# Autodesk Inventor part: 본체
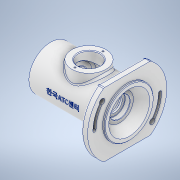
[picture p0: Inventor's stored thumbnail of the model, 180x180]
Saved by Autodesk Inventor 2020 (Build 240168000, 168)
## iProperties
Created: 2022-05
Part Number: 본체
Material: 알루미늄 6061
Document SubType Name: Modeling
Designer: Student
Mass: 685.464 g
Surface Area: 627.299 cm^2
Volume: 253.876 cm^3
Density: 2.7 g/cm^3
Appearance: 알루미늄 - 평지
Author: Student
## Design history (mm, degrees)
sketch "스케치1"
  geometry: L1 (-97.293, 0)-(97.293, 0); L2 (-51, 0)-(-51, 32); L3 (-51, 32)-(51, 32); L4 (51, 32)-(51, 58); L5 (51, 58)-(61, 58); L6 (61, 58)-(61, 36); L7 (61, 36)-(64, 36); L8 (64, 36)-(64, 0); 4 further points
  constraints: 16 end point, 4 perpendicular, 3 coincident, 3 midpoint, 2 horizontal, 2 point on line, 1 parallel, 1 vertical, 1 vertical alignment
  dimensions: "d5" = 64 diameter of L3 L1; "d6" = 116 diameter of L5 L1; "d7" = 72 diameter of L7 L1; "d8" = 102 distance between parallel lines of L4 L2; "d9" = 13 distance between parallel lines of L8 L4; "d10" = 3 distance of L6.end L7.end
revolve "회전1" sketch "스케치1" stored, may be unused: angle "d11" = 90 deg
sketch "스케치2"
  geometry: L1 (-76.744, 0)-(76.744, 0); L2 (-51, 22.5)-(-43, 22.5); L3 (-43, 22.5)-(-43, 24); L4 (-43, 24)-(-40, 24); L5 (-40, 24)-(-40, 22.5); L6 (-40, 22.5)-(-29, 22.5); L7 (-29, 22.5)-(-29, 17.5); L8 (-29, 17.5)-(-26.75, 17.5); L9 (-26.75, 17.5)-(-26.75, 18.5); L10 (-26.75, 18.5)-(-25, 18.5); L11 (-25, 18.5)-(-25, 17.5); L12 (-25, 17.5)-(-14, 17.5); L13 (-14, 17.5)-(-14, 27); L14 (-14, 27)-(24, 27); L15 (24, 27)-(24, 17.5); L16 (24, 17.5)-(35, 17.5); L17 (35, 17.5)-(35, 15); L18 (35, 15)-(40, 15); L19 (40, 15)-(40, 11); L20 (40, 11)-(42.7, 11); L21 (42.7, 11)-(42.7, 15); L22 (42.7, 15)-(49.3, 15); L23 (64, -36)-(64, 36) reference; L24 (64, 30)-(64, 0); L25 (-51, -32)-(-51, 32) reference; L26 (-51, 22.5)-(-51, 0); L27 (50, 15.404)-(50, 20); L28 (50, 20)-(64, 30); L29 (49.3, 15)-(50, 15.404); 5 further points
  constraints: 54 end point, 17 perpendicular, 10 point on line, 2 coincident, 2 horizontal, 2 midpoint, 1 parallel, 1 vertical
  dimensions: "d12" = 45 diameter of L2 L1; "d13" = 48 diameter of L4 L1; "d14" = 54 diameter of L14 L1; "d15" = 30 diameter of L18 L1; "d17" = 60 diameter of L24.start L1; "d18" = 40 diameter of L27.end L1; "d19" = 30 diameter of L22 L1; "d20" = 22 diameter of L20 L1; "d21" = 37 diameter of L10 L1; "d22" = 35 diameter of L12 L1; "d23" = 8 distance of L2.start L2.end; "d24" = 3 distance of L3.end L4.end; "d25" = 11 distance of L11.end L12.end; "d26" = 11 distance of L15.end L16.end; "d27" = 14 distance from line of L23 L27.end; "d28" = 5 distance of L17.end L18.end; "d29" = 29 distance between parallel lines of L23 L17; "d30" = 22 distance between parallel lines of L7 L26; "d32" = 1.75 distance of L9.end L10.end; "d33" = 4 distance between parallel lines of L7 L11; "d35" = 150 deg angle of L22 L29; "d36" = 0.7 horizontal distance of L27.start L22.end; "d37" = 7.3 distance between parallel lines of L27 L21
revolve "회전2" sketch "스케치2" stored, may be unused: angle "d34" = 90 deg
node "작업 평면1"
sketch "스케치3"
  geometry: L1 (51, 32)-(51, -32) reference; C1 r 25 at (-5, 0); 1 further point
  constraints: 1 centre point, 1 horizontal alignment
  dimensions: "d39" = 25 radius of C1; "d40" = 56 distance from line of L1 C1.centre
extrude "돌출1" join sketch "스케치3" stored distance "d41" = 10; taper "d42" = 0 deg
sketch "스케치4"
  geometry: C1 r 25 at (0, 0) reference; 1 further point
hole "구멍1" sketch "스케치4" at (0, 0) diameter "d43" = 32; stored, may be unused: countersink angle "d47" = 90 deg, drill point angle "d49" = 0 deg; dims "d44" = 6, "d45" = 4, "d46" = 2, "d48" = 20
sketch "스케치7"
  geometry: L1 (-33.985, 47)-(33.985, 47); L2 (-33.985, -47)-(33.985, -47); A1 r 58 centre (0, 0) between (-33.985, 47) and (-33.985, -47) reference; A2 r 58 centre (0, 0) between (-33.985, -47) and (33.985, -47); A3 r 58 centre (0, 0) between (33.985, 47) and (-33.985, 47); 1 further point
  constraints: 8 point on circle, 4 end point, 2 centre point, 1 coincident, 1 horizontal, 1 parallel
  dimensions: "d68" = 47 distance from line of point (0, 0) L1; "d69" = 47 distance from line of point (0, 0) L2
extrude "돌출4" cut sketch "스케치7" extent not by distance; stored distance "d70" = 0; taper "d71" = 0 deg
sketch "스케치8"
  geometry: C1 r 25 at (0, 0) reference; 2 further points
  constraints: 1 vertical alignment
  dimensions: "d72" = 20.5 distance of C1.centre point (0, 20.5)
hole "구멍2" sketch "스케치8" at (0, 20.5) diameter "d73" = 2.459; stored, may be unused: countersink angle "d77" = 90 deg, drill point angle "d79" = 118 deg; dims "d74" = 6, "d75" = 4, "d76" = 2, "d78" = 8
node "작업 평면2"
sketch "스케치9"
  geometry: L1 (61, -47)-(61, 47) reference; 2 further points
  constraints: 1 horizontal alignment, 1 other
  dimensions: "d84" = 62 distance from line of L1 point (-1, 0)
feature "엠보싱1" sketch "스케치9" dims "d12" = 45, "d13" = 48, "d14" = 54, "d15" = 30, "d17" = 60, "d18" = 40, "d19" = 30, "d20" = 22, "d21" = 37, "d22" = 35, "d23" = 8, "d24" = 3, "d25" = 11, "d26" = 11, "d27" = 14, "d28" = 5, "d29" = 29, "d30" = 22, "d32" = 1.75, "d33" = 4, "d35" = 150 deg, "d36" = 0.7, "d37" = 7.3, "d85" = 0.5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
fillet "모깎기1" dims "d87" = 0.5
fillet "모깎기2" dims "d88" = 0.6
feature "스레드1" dims "d89" = 18, "d90" = 0
fillet "모깎기3" dims "d91" = 3
chamfer "모따기1" distance "d92" = 1; stored, may be unused: second distance "d93" = 2, angle "d94" = 45 deg
sketch "스케치11"
  geometry: L1 (0, 0)-(-47.496, 0); L2 (0, 0)-(42.689, 0); L3 (-36.77, -30.854)-(0, 0); L4 (0, 0)-(36.77, 30.854); A1 r 48 centre (0, 0) between (-48, 0) and (-36.77, -30.854); A2 r 50.25 centre (0, 0) between (-50.25, 0) and (-38.494, -32.3); A3 r 45.75 centre (0, 0) between (-45.75, 0) and (-35.047, -29.408); A4 r 2.25 centre (-48, 0) between (-45.75, 0) and (-50.25, 0); A5 r 2.25 centre (-36.77, -30.854) between (-38.494, -32.3) and (-35.047, -29.408); A6 r 48 centre (0, 0) between (48, 0) and (36.77, 30.854); A7 r 50.25 centre (0, 0) between (50.25, 0) and (38.494, 32.3); A8 r 45.75 centre (0, 0) between (45.75, 0) and (35.047, 29.408); A9 r 2.25 centre (48, 0) between (45.75, 0) and (50.25, 0); A10 r 2.25 centre (36.77, 30.854) between (38.494, 32.3) and (35.047, 29.408); A11 r 52 centre (0, 0) between (52, 0) and (39.834, 33.425); A12 r 4 centre (48, 0) between (44, 0) and (52, 0); A13 r 44 centre (0, 0) between (44, 0) and (33.706, 28.283); A14 r 4 centre (36.77, 30.854) between (39.834, 33.425) and (33.706, 28.283); A15 r 44 centre (0, 0) between (-44, 0) and (-33.706, -28.283); A16 r 4 centre (-48, 0) between (-44, 0) and (-52, 0); A17 r 52 centre (0, 0) between (-52, 0) and (-39.834, -33.425); A18 r 4 centre (-36.77, -30.854) between (-39.834, -33.425) and (-33.706, -28.283)
  constraints: 37 point on circle, 18 centre point, 8 end point, 8 tangent, 4 point on line, 1 coincident, 1 horizontal, 1 horizontal alignment, 6 other
  dimensions: "d104" = 4.5 radial gap between concentric circles of A3 A2; "d105" = 48 radius of A1; "d106" = 48 radius of A6; "d107" = 4.5 radial gap between concentric circles of A8 A7; "d108" = 40 deg angle of L2 L4; "d109" = 40 deg angle of L1 L3; "d110" = 8 radial gap between concentric circles of A17 A15; "d111" = 8 radial gap between concentric circles of A11 A13
extrude "돌출7" cut sketch "스케치11" extent not by distance; stored distance "d112" = 4.4; taper "d113" = 0 deg
extrude "돌출8" cut sketch "스케치11" distance "d114" = 4.4; taper "d115" = 0 deg
sketch "스케치12"
  geometry: C1 r 4 at (-36.77, -30.854); C2 r 4 at (36.77, 30.854); A1 r 4 centre (-36.77, -30.854) between (-39.834, -33.425) and (-33.706, -28.283) reference; A2 r 4 centre (36.77, 30.854) between (39.834, 33.425) and (33.706, 28.283) reference; 5 further points
  constraints: 2 centre point, 2 coincident
  dimensions: "d116" = 4 radius of C1; "d117" = 4 radius of C2
extrude "돌출9" cut sketch "스케치12" extent not by distance; stored distance "d118" = 0; taper "d119" = 0 deg
fillet "모깎기4" dims "d120" = 3
fillet "모깎기5" dims "d121" = 3
node "솔리드1"
pattern_circular "원형 패턴1" dims angle "d81" = 360 deg
feature "A9D066F2-1C7D-4E18-AEED-F7BC21143FA4" dims "d89" = 18, "d90" = 0
other parameters: "d38" = 38, "d83" = 67.75
